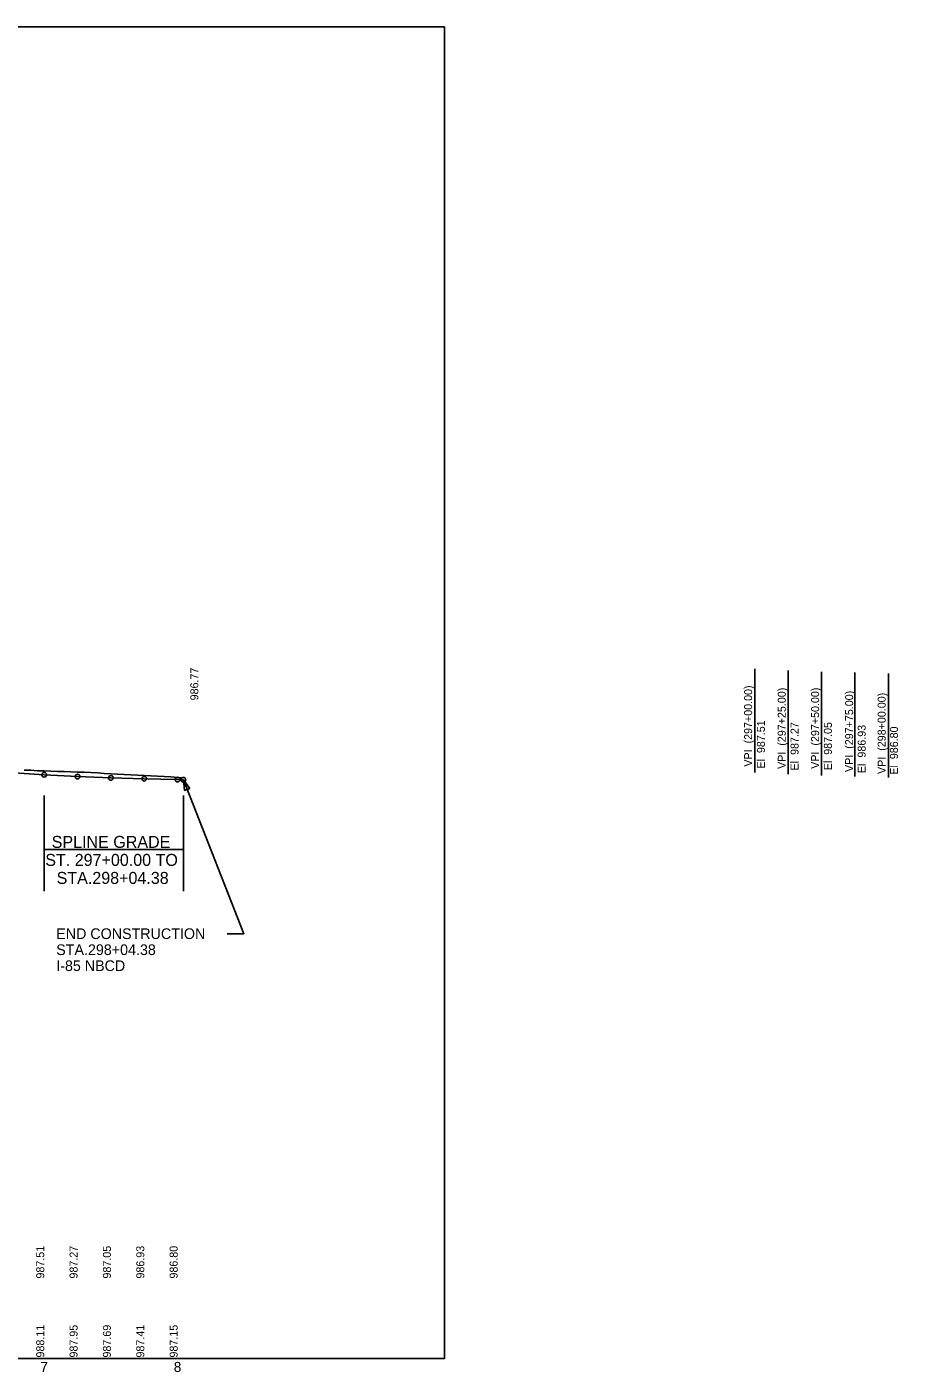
# Model space of a CAD drawing. Extents: x 1608361 to 16979326, y 1092015 to 12565288.
# Drawn here: x 16978673 to 16979326, y 12564278 to 12565286 of the extents above; entities that cross this region are included whole.
import ezdxf

# ---------------------------------------------------------------- set-up
doc = ezdxf.new("R2010")
doc.units = 0
for name, color, linetype in [('Default', 7, 'Continuous'), ('RD_EX_BldgApp_txCode', 7, 'Continuous'), ('RD_EX_H2O', 7, 'Continuous'), ('RD_EX_RW_Approx', 7, 'Continuous'), ('RD_EX_SU_Water', 7, 'Continuous'), ('RD_EX_UT', 7, 'Continuous'), ('RD_HC_Data_Tic_Rel', 7, 'Continuous'), ('RD_HC_TX_Rel_Sta50', 7, 'Continuous'), ('RD_PD_Final_TX', 7, 'Continuous'), ('RD_SHT_Snap', 7, 'Continuous'), ('TEXT2', 7, 'Continuous')]:
    doc.layers.add(name, color=color, linetype=linetype)

msp = doc.modelspace()

# ---------------------------------------------------------------- linework, layer by layer
at = {"layer": 'Default'}
msp.add_lwpolyline([(16977485.6, 12564287.8), (16978985.6, 12564287.8), (16978985.6, 12565286), (16977485.6, 12565286)], close=True, dxfattribs=at)
at = {"layer": 'RD_EX_BldgApp_txCode'}
for p, q in [((16978685.6, 12564638.1), (16978685.6, 12564709.9)), ((16978789.9, 12564638.1), (16978789.9, 12564709.9)), ((16978685.6, 12564669.4), (16978789.9, 12564669.4))]:
    msp.add_line(p, q, dxfattribs=at)
at = {"layer": 'RD_EX_H2O'}
msp.add_lwpolyline([(16978670.6, 12564728.9), (16978675.6, 12564728.8), (16978680.6, 12564728.5), (16978685.6, 12564728.3), (16978690.6, 12564728.1), (16978695.6, 12564728), (16978700.6, 12564727.8), (16978705.6, 12564727.7), (16978710.6, 12564727.5), (16978715.6, 12564727.3), (16978720.6, 12564727.1), (16978725.6, 12564726.8), (16978730.6, 12564726.5), (16978735.6, 12564726.2), (16978740.6, 12564725.9), (16978745.6, 12564725.6), (16978750.6, 12564725.4), (16978755.6, 12564725.1), (16978760.6, 12564724.8), (16978765.6, 12564724.6), (16978770.6, 12564724.4), (16978775.6, 12564724.2), (16978780.6, 12564723.9), (16978785.6, 12564723.5), (16978789.9, 12564723.2)], dxfattribs=at)
at = {"layer": 'RD_EX_RW_Approx'}
for centre in [(16978685.6, 12564725.4), (16978710.6, 12564724.1), (16978735.6, 12564723.1), (16978760.6, 12564722.5), (16978785.6, 12564721.8), (16978789.9, 12564721.7)]:
    msp.add_circle(centre, 1.75, dxfattribs=at)
at = {"layer": 'RD_EX_UT'}
msp.add_line((16972985.6, 12564287.8), (16978789.9, 12564287.8), dxfattribs=at)
at = {"layer": 'RD_HC_Data_Tic_Rel'}
for p, q in [((16979218.3, 12564727.1), (16979218.3, 12564804.9)), ((16979243.3, 12564725.9), (16979243.3, 12564803.7)), ((16979268.3, 12564724.8), (16979268.3, 12564802.6)), ((16979293.3, 12564724.2), (16979293.3, 12564802)), ((16979318.3, 12564723.5), (16979318.3, 12564801.4))]:
    msp.add_line(p, q, dxfattribs=at)
at = {"layer": 'RD_HC_TX_Rel_Sta50'}
for p, q in [((16978655.6, 12564727.3), (16978685.6, 12564725.4)), ((16978685.6, 12564725.4), (16978710.6, 12564724.1)), ((16978710.6, 12564724.1), (16978735.6, 12564723.1)), ((16978735.6, 12564723.1), (16978760.6, 12564722.5)), ((16978760.6, 12564722.5), (16978785.6, 12564721.8)), ((16978785.6, 12564721.8), (16978789.9, 12564721.7))]:
    msp.add_line(p, q, dxfattribs=at)
at = {"layer": 'RD_SHT_Snap'}
msp.add_lwpolyline([(16978822.6, 12564606.3), (16978835.2, 12564606.3), (16978789.9, 12564721.7)], dxfattribs=at)
msp.add_lwpolyline([(16978794.7, 12564715.2), (16978789.9, 12564721.7), (16978790.8, 12564713.7)], close=True, dxfattribs=at)

# ---------------------------------------------------------------- texts
at = {"layer": 'RD_EX_BldgApp_txCode'}
for s, p in [('SPLINE GRADE', (16978691.2, 12564670.6)), ('ST. 297+00.00 TO', (16978686.4, 12564657.1)), ('STA.298+04.38', (16978694.9, 12564643.6))]:
    msp.add_text(s, height=9, dxfattribs=at).set_placement(p)
at = {"layer": 'RD_EX_RW_Approx'}
for s, p in [('986.77', (16978801.1, 12564781.2)), ('VPI  (297+00.00)', (16979216.2, 12564731.5)), ('VPI  (297+25.00)', (16979241.4, 12564729.8)), ('VPI  (297+50.00)', (16979266.4, 12564729.9)), ('VPI  (297+75.00)', (16979291.9, 12564727.5)), ('VPI  (298+00.00)', (16979316.3, 12564726)), ('El  987.51', (16979225.8, 12564730.1)), ('El  987.27', (16979251, 12564728.7)), ('El  987.05', (16979276, 12564728.8)), ('El  986.93', (16979301.3, 12564726.7)), ('El  986.80', (16979325.5, 12564725.5))]:
    msp.add_text(s, height=6, rotation=90, dxfattribs=at).set_placement(p)
at = {"layer": 'RD_EX_SU_Water'}
for s, p in [('987.51', (16978685.6, 12564347.8)), ('987.27', (16978710.6, 12564347.8)), ('987.05', (16978735.6, 12564347.8)), ('986.93', (16978760.6, 12564347.8)), ('986.80', (16978785.6, 12564347.8))]:
    msp.add_text(s, height=6, rotation=90, dxfattribs=at).set_placement(p)
at = {"layer": 'RD_PD_Final_TX'}
for s, p in [('7', (16978682.7, 12564277.8)), ('7', (16978682.8, 12564277.8)), ('8', (16978782.7, 12564277.8)), ('8', (16978782.8, 12564277.8))]:
    msp.add_text(s, height=7.5, dxfattribs=at).set_placement(p)
at = {"layer": 'RD_SHT_Snap'}
for s, p in [('END CONSTRUCTION', (16978694.6, 12564602.3)), ('STA.298+04.38 ', (16978694.6, 12564590.3)), ('I-85 NBCD', (16978694.6, 12564578.3))]:
    msp.add_text(s, height=8, dxfattribs=at).set_placement(p)
at = {"layer": 'TEXT2'}
for s, p in [('988.11', (16978685.6, 12564288.6)), ('987.95', (16978710.6, 12564288.6)), ('987.69', (16978735.6, 12564288.6)), ('987.41', (16978760.6, 12564288.6)), ('987.15', (16978785.6, 12564288.6))]:
    msp.add_text(s, height=6, rotation=90, dxfattribs=at).set_placement(p)

doc.saveas('drawing.dxf')
